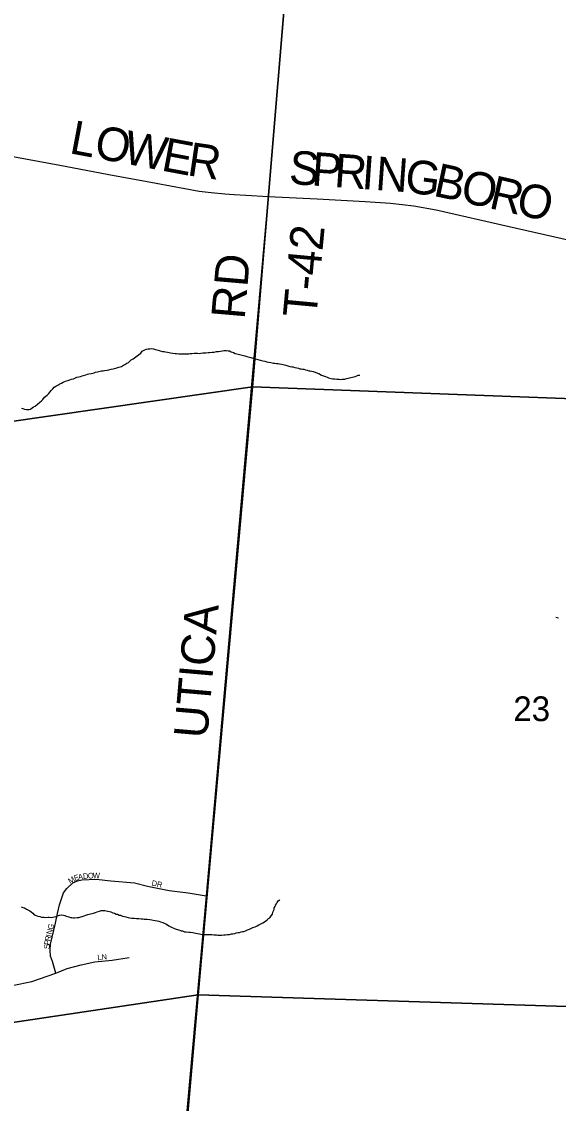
# Model space of a CAD drawing. Extents: x 0 to 1064, y 0 to 440.
# Drawn here: x 280.36 to 294.9, y 317.7 to 347.01 of the extents above; entities that cross this region are included whole.
import ezdxf

# ---------------------------------------------------------------- set-up
doc = ezdxf.new("R2010")
doc.units = 0
for name, color, linetype in [('GM_X_County_Road', 7, 'Continuous'), ('GM_X_County_Road_Text', 7, 'Continuous'), ('GM_X_Minor_River', 7, 'Continuous'), ('GM_X_Section', 7, 'Continuous'), ('GM_X_Section_Text', 7, 'Continuous'), ('GM_X_Township_Road', 7, 'Continuous'), ('GM_X_Township_Road_Text', 7, 'Continuous'), ('GM_X_Township_Subdivision', 7, 'Continuous'), ('GM_X_Township_Subdivision_Text', 7, 'Continuous')]:
    doc.layers.add(name, color=color, linetype=linetype)

msp = doc.modelspace()

# ---------------------------------------------------------------- linework, layer by layer
at = {"layer": 'GM_X_County_Road'}
msp.add_lwpolyline([(279.878, 343.398), (281.395, 343.118), (282.866, 342.837), (283.619, 342.702), (285.169, 342.416), (285.497, 342.375), (285.869, 342.339), (286.122, 342.327), (286.437, 342.308), (287.042, 342.269), (288.367, 342.202), (289.667, 342.134), (290.351, 342.088), (290.99, 342.015), (291.596, 341.909), (293.568, 341.454), (295.682, 340.975)], dxfattribs=at)
at = {"layer": 'GM_X_Minor_River'}
for points in [[(280.353, 336.536), (280.39, 336.523), (280.432, 336.51), (280.486, 336.502), (280.529, 336.501), (280.565, 336.5), (280.602, 336.511), (280.645, 336.541), (280.683, 336.57), (280.726, 336.587), (280.788, 336.64), (280.85, 336.694), (280.894, 336.735), (280.937, 336.77), (280.981, 336.83), (281.049, 336.883), (281.093, 336.937), (281.125, 336.973), (281.169, 337.026), (281.206, 337.056), (281.244, 337.103), (281.287, 337.127), (281.336, 337.156), (281.392, 337.191), (281.435, 337.214), (281.484, 337.243), (281.546, 337.266), (281.613, 337.283), (281.668, 337.299), (281.711, 337.317), (281.76, 337.334), (281.822, 337.356), (281.858, 337.374), (281.907, 337.385), (281.956, 337.396), (281.999, 337.413), (282.036, 337.424), (282.097, 337.441), (282.14, 337.452), (282.177, 337.463), (282.244, 337.473), (282.287, 337.485), (282.324, 337.496), (282.361, 337.507), (282.416, 337.518), (282.489, 337.534), (282.526, 337.545), (282.568, 337.55), (282.605, 337.556), (282.672, 337.566), (282.721, 337.577), (282.782, 337.588), (282.837, 337.598), (282.874, 337.61), (282.941, 337.626), (282.99, 337.649), (283.064, 337.666), (283.119, 337.701), (283.156, 337.718), (283.212, 337.753), (283.255, 337.776), (283.324, 337.842), (283.379, 337.871), (283.416, 337.9), (283.454, 337.93), (283.522, 337.977), (283.584, 338.024), (283.628, 338.077), (283.695, 338.112), (283.739, 338.135), (283.787, 338.146), (283.83, 338.145), (283.885, 338.15), (283.933, 338.143), (283.988, 338.129), (284.06, 338.109), (284.114, 338.089), (284.175, 338.07), (284.223, 338.068), (284.26, 338.061), (284.314, 338.048), (284.356, 338.041), (284.393, 338.034), (284.459, 338.026), (284.52, 338.018), (284.556, 338.017), (284.617, 338.01), (284.708, 338.008), (284.745, 338.007), (284.799, 338.005), (284.842, 338.01), (284.891, 338.009), (284.927, 338.014)], [(284.927, 338.014), (284.97, 338.013), (285.031, 338.024), (285.073, 338.023), (285.128, 338.021), (285.165, 338.02), (285.213, 338.025), (285.268, 338.03), (285.347, 338.034), (285.414, 338.045), (285.451, 338.044), (285.518, 338.048), (285.573, 338.053), (285.64, 338.069), (285.689, 338.074), (285.75, 338.079), (285.799, 338.09), (285.841, 338.095), (285.902, 338.093), (285.951, 338.092), (285.993, 338.085), (286.035, 338.065), (286.101, 338.039), (286.149, 338.014), (286.186, 338.007), (286.222, 338), (286.258, 337.987), (286.3, 337.98), (286.367, 337.966), (286.409, 337.953), (286.464, 337.939), (286.5, 337.926), (286.572, 337.906), (286.627, 337.892), (286.693, 337.873), (286.759, 337.853), (286.826, 337.833), (286.898, 337.819), (286.947, 337.805), (287.007, 337.792), (287.049, 337.785), (287.11, 337.771), (287.182, 337.757), (287.219, 337.756), (287.261, 337.749), (287.31, 337.742), (287.346, 337.735), (287.401, 337.727), (287.449, 337.714), (287.522, 337.7), (287.57, 337.686), (287.624, 337.667), (287.679, 337.659), (287.715, 337.658), (287.763, 337.639), (287.818, 337.625), (287.86, 337.618), (287.896, 337.605), (287.933, 337.604), (287.969, 337.591), (288.005, 337.59), (288.053, 337.577), (288.096, 337.564), (288.138, 337.55), (288.174, 337.55), (288.211, 337.536), (288.259, 337.529), (288.313, 337.51), (288.373, 337.484), (288.409, 337.471), (288.481, 337.432), (288.542, 337.413), (288.596, 337.393), (288.638, 337.374), (288.674, 337.361), (288.71, 337.348), (288.747, 337.341), (288.795, 337.333), (288.837, 337.326), (288.898, 337.325), (288.959, 337.317), (289.001, 337.316), (289.044, 337.321), (289.081, 337.32), (289.117, 337.325), (289.16, 337.336), (289.203, 337.347), (289.246, 337.358), (289.282, 337.37), (289.325, 337.375), (289.362, 337.386), (289.399, 337.397), (289.442, 337.408), (289.478, 337.426), (289.527, 337.43)], [(294.91, 330.849), (294.874, 330.856), (294.838, 330.863)], [(280.348, 323.024), (280.391, 323.01), (280.433, 322.997), (280.487, 322.965), (280.541, 322.94), (280.577, 322.915), (280.612, 322.889), (280.66, 322.852), (280.696, 322.814), (280.756, 322.788), (280.798, 322.775), (280.852, 322.762), (280.901, 322.748), (280.961, 322.747), (281.016, 322.739), (281.065, 322.744), (281.107, 322.743), (281.156, 322.742), (281.205, 322.747), (281.247, 322.758)], [(281.247, 322.758), (281.29, 322.769), (281.333, 322.786), (281.388, 322.803), (281.449, 322.807), (281.492, 322.8), (281.528, 322.793), (281.564, 322.774), (281.6, 322.767), (281.637, 322.754), (281.679, 322.741), (281.715, 322.74), (281.752, 322.733), (281.794, 322.732), (281.861, 322.736), (281.91, 322.741), (281.965, 322.752), (282.002, 322.763), (282.051, 322.786), (282.1, 322.803), (282.149, 322.82), (282.192, 322.831), (282.228, 322.837), (282.271, 322.842), (282.308, 322.859), (282.363, 322.87), (282.406, 322.893), (282.467, 322.91), (282.516, 322.927), (282.553, 322.926), (282.614, 322.924), (282.65, 322.917), (282.698, 322.91), (282.735, 322.903), (282.777, 322.89), (282.831, 322.864), (282.873, 322.851), (282.921, 322.831), (282.958, 322.824), (283, 322.805), (283.036, 322.798), (283.09, 322.778), (283.145, 322.765), (283.181, 322.752), (283.241, 322.738), (283.278, 322.731), (283.344, 322.717), (283.411, 322.716), (283.472, 322.708), (283.532, 322.707), (283.593, 322.699), (283.642, 322.698), (283.678, 322.697), (283.721, 322.696), (283.763, 322.689), (283.83, 322.681), (283.884, 322.673), (283.92, 322.666), (283.975, 322.653), (284.035, 322.645), (284.078, 322.638), (284.12, 322.619), (284.186, 322.599), (284.222, 322.586), (284.264, 322.566), (284.312, 322.541), (284.348, 322.516), (284.384, 322.491), (284.438, 322.465), (284.48, 322.446), (284.522, 322.432), (284.607, 322.4), (284.643, 322.393), (284.679, 322.38), (284.716, 322.373), (284.776, 322.353), (284.818, 322.346), (284.891, 322.338), (284.927, 322.337), (284.994, 322.329), (285.03, 322.322), (285.079, 322.315), (285.127, 322.308), (285.176, 322.294), (285.218, 322.287), (285.309, 322.279), (285.364, 322.277), (285.4, 322.277), (285.437, 322.276), (285.473, 322.275), (285.51, 322.274), (285.57, 322.266), (285.607, 322.265), (285.643, 322.264), (285.679, 322.263), (285.728, 322.262), (285.777, 322.261), (285.838, 322.266), (285.886, 322.264), (285.941, 322.275), (285.99, 322.28)], [(285.99, 322.28), (286.045, 322.291), (286.082, 322.296), (286.137, 322.307), (286.174, 322.324), (286.216, 322.329), (286.259, 322.334), (286.308, 322.351), (286.345, 322.356), (286.381, 322.361), (286.424, 322.379), (286.48, 322.401), (286.529, 322.418), (286.572, 322.442), (286.621, 322.465), (286.688, 322.487), (286.738, 322.511), (286.787, 322.54), (286.855, 322.574), (286.892, 322.592), (286.941, 322.621), (286.978, 322.65), (287.015, 322.674), (287.047, 322.71), (287.084, 322.733), (287.122, 322.781), (287.153, 322.828), (287.167, 322.883), (287.186, 322.919), (287.199, 322.955), (287.206, 322.997), (287.225, 323.033), (287.239, 323.076), (287.264, 323.112), (287.283, 323.147), (287.314, 323.189), (287.358, 323.213)]]:
    msp.add_lwpolyline(points, dxfattribs=at)
at = {"layer": 'GM_X_Section'}
for points in [[(271.58, 351.945), (287.989, 353.559), (286.615, 337.115), (270.211, 334.756)], [(287.989, 353.559), (304.793, 352.705), (303.284, 336.488), (286.615, 337.115)], [(270.211, 334.756), (286.615, 337.115), (285.143, 320.643), (268.72, 318.199)], [(286.615, 337.115), (303.284, 336.488), (301.712, 320.115), (285.143, 320.643)], [(268.72, 318.199), (285.143, 320.643), (283.717, 304.339), (267.132, 301.372)], [(285.143, 320.643), (301.712, 320.115), (300.126, 302.432), (283.717, 304.339)]]:
    msp.add_lwpolyline(points, close=True, dxfattribs=at)
at = {"layer": 'GM_X_Township_Road'}
msp.add_lwpolyline([(287.042, 342.269), (285.355, 323.327), (284.545, 314.283)], dxfattribs=at)
at = {"layer": 'GM_X_Township_Subdivision'}
for points in [[(281.289, 321.233), (281.194, 321.55), (281.142, 321.687), (281.132, 321.85), (281.137, 322.013), (281.184, 322.202), (281.277, 322.585), (281.329, 322.844), (281.381, 323.083), (281.494, 323.404), (281.583, 323.52), (281.743, 323.673), (281.873, 323.727), (281.992, 323.756), (282.375, 323.777), (282.779, 323.735), (283.421, 323.673), (283.773, 323.59), (284.353, 323.466), (284.871, 323.404), (285.355, 323.327)], [(277.037, 321.573), (277.346, 321.545), (277.598, 321.485), (277.851, 321.379), (278.117, 321.226), (278.303, 321.073), (278.496, 320.933), (278.709, 320.827), (278.962, 320.78), (279.367, 320.794), (280.099, 320.9), (280.631, 321.007), (281.289, 321.233), (281.595, 321.352), (281.967, 321.459), (282.339, 321.538), (282.811, 321.578), (283.27, 321.658)]]:
    msp.add_lwpolyline(points, dxfattribs=at)

# ---------------------------------------------------------------- texts
at = {"layer": 'GM_X_County_Road_Text'}
for s, rotation, p in [('L', 349.3406, (281.625, 343.447)), ('O', 349.3408, (282.294, 343.321)), ('W', 349.3429, (283.08, 343.173)), ('E', 349.3679, (284.115, 342.978)), ('R', 351.551, (284.821, 342.847)), ('S', 355.977, (287.587, 342.613)), ('P', 355.977, (288.199, 342.57)), ('R', 355.9767, (288.811, 342.527)), ('I', 355.9803, (289.555, 342.475)), ('N', 355.8326, (289.927, 342.449)), ('G', 352.5917, (290.712, 342.392)), ('B', 347.9131, (291.486, 342.292)), ('O', 347.2661, (292.213, 342.136)), ('R', 347.2494, (292.993, 341.96)), ('O', 347.2508, (293.722, 341.795))]:
    msp.add_text(s, height=0.909, rotation=rotation, dxfattribs=at).set_placement(p)
at = {"layer": 'GM_X_Section_Text'}
msp.add_text('23', height=0.6697, rotation=0, dxfattribs=at).set_placement((293.683, 328.057))
at = {"layer": 'GM_X_Township_Road_Text'}
for s, rotation, p in [('T-42', 84.6762, (288.341, 338.963)), ('RD', 85.0293, (286.4, 338.927)), ('UTICA', 85.0499, (285.386, 327.567))]:
    msp.add_text(s, height=0.9091, rotation=rotation, dxfattribs=at).set_placement(p)
at = {"layer": 'GM_X_Township_Subdivision_Text'}
for s, height, rotation, p in [('M', 0.152, 31.7447, (281.675, 323.644)), ('E', 0.152, 18.2276, (281.803, 323.724)), ('A', 0.152, 10.0839, (281.899, 323.756)), ('D', 0.152, 4.6166, (282.026, 323.779)), ('O', 0.152, 3.9159, (282.159, 323.79)), ('W', 0.152, 359.3107, (282.288, 323.799)), ('DR', 0.1515, 348.1073, (283.869, 323.604)), ('N', 0.152, 76.6992, (281.173, 322.268)), ('G', 0.152, 76.6992, (281.204, 322.397)), ('P', 0.152, 81.8583, (281.116, 321.984)), ('R', 0.152, 77.0418, (281.131, 322.086)), ('I', 0.152, 76.6743, (281.158, 322.203)), ('S', 0.152, 88.6341, (281.114, 321.882)), ('LN', 0.1515, 6.0054, (282.42, 321.578))]:
    msp.add_text(s, height=height, rotation=rotation, dxfattribs=at).set_placement(p)

doc.saveas('drawing.dxf')
